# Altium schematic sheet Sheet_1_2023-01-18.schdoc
size 318 x 214 mm
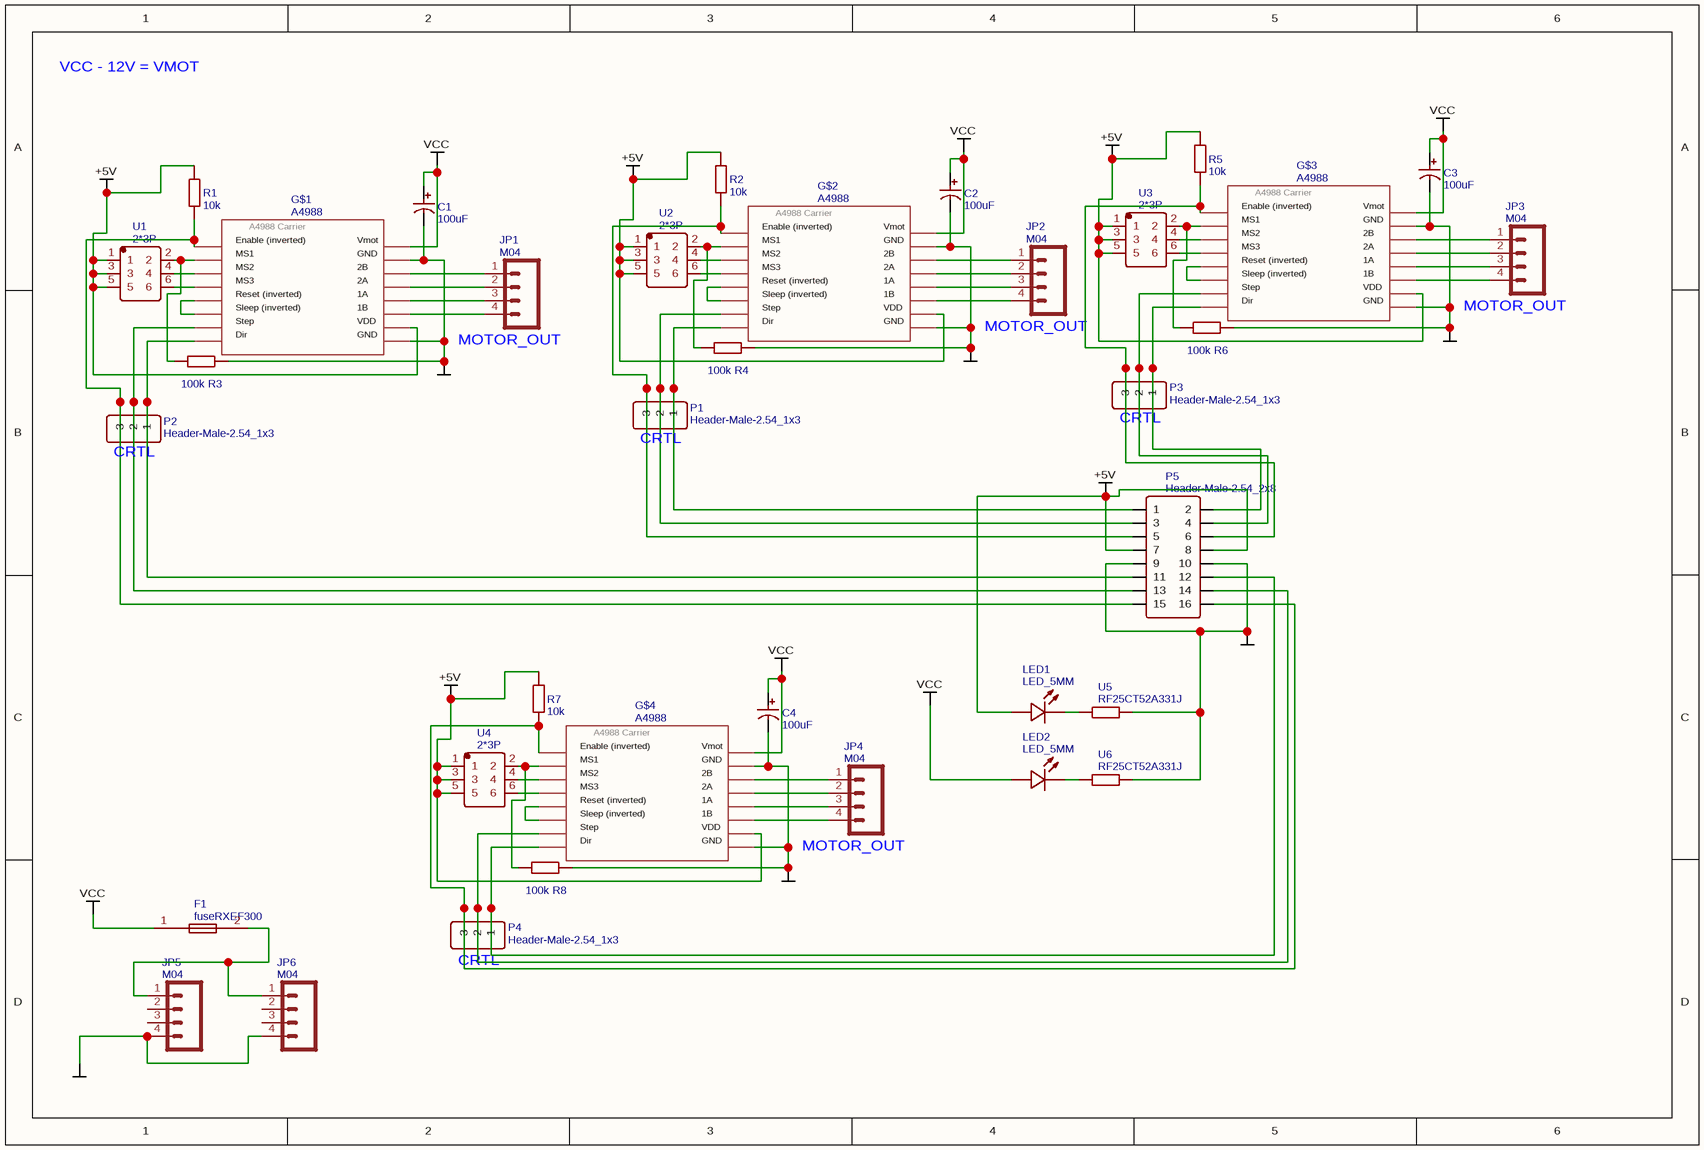
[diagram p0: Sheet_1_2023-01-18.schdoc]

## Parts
C1  100uF  [CAP-8*5]
C2  100uF  [CAP-8*5]
C3  100uF  [CAP-8*5]
C4  100uF  [CAP-8*5]
F1  fuseRXEF300  [F-3.00A-60V]
G$1  A4988  [A4988BREAKOUT]
G$2  A4988  [A4988BREAKOUT]
G$3  A4988  [A4988BREAKOUT]
G$4  A4988  [A4988BREAKOUT]
JP1  M04  [SCREWTERMINAL-3.5MM-4]
JP2  M04  [SCREWTERMINAL-3.5MM-4]
JP3  M04  [SCREWTERMINAL-3.5MM-4]
JP4  M04  [SCREWTERMINAL-3.5MM-4]
JP5  M04  [SCREWTERMINAL-3.5MM-4]
JP6  M04  [SCREWTERMINAL-3.5MM-4]
LED1  LED_5MM  [LED 5MM]
LED2  LED_5MM  [LED 5MM]
P1  Header-Male-2.54_1x3  [HDR-3X1/2.54]
P2  Header-Male-2.54_1x3  [HDR-3X1/2.54]
P3  Header-Male-2.54_1x3  [HDR-3X1/2.54]
P4  Header-Male-2.54_1x3  [HDR-3X1/2.54]
P5  Header-Male-2.54_2x8  [HDR-8X2/2.54]
R1  10k  [AXIAL-0.6]
R2  10k  [AXIAL-0.6]
R3  100k  [AXIAL-0.6]
R4  100k  [AXIAL-0.6]
R5  10k  [AXIAL-0.6]
R6  100k  [AXIAL-0.6]
R7  10k  [AXIAL-0.6]
R8  100k  [AXIAL-0.6]
U1  2*3P  [HDR-2.0-2X3P]
U2  2*3P  [HDR-2.0-2X3P]
U3  2*3P  [HDR-2.0-2X3P]
U4  2*3P  [HDR-2.0-2X3P]
U5  RF25CT52A331J  [AXIAL-6.5X2.3(1/4W)]
U6  RF25CT52A331J  [AXIAL-6.5X2.3(1/4W)]

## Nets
+5V: G$1.VDD G$2.VDD G$3.VDD G$4.VDD LED1.2(A) P5.7 P5.8 R1.2 R2.2 R5.2 R7.2 U1.1 U1.3 U1.5 U2.1 U2.3 U2.5 U3.1 U3.3 U3.5 U4.1 U4.3 U4.5
GND: C1.2 C2.2 C3.2 C4.2 G$1.GND G$1.GND@0(GND) G$2.GND G$2.GND@0(GND) G$3.GND G$3.GND@0(GND) G$4.GND G$4.GND@0(GND) JP5.4 JP6.4 P5.9 P5.10 R3.2 R4.2 R6.2 R8.2 U5.2 U6.2
VCC: C1.1 C2.1 C3.1 C4.1 F1.1 G$1.VMOT G$2.VMOT G$3.VMOT G$4.VMOT LED2.2(A)
NetF1_2: F1.2 JP5.1 JP6.1
NetG$1_1A: G$1.1A JP1.3
NetG$1_1B: G$1.1B JP1.4
NetG$1_2A: G$1.2A JP1.2
NetG$1_2B: G$1.2B JP1.1
NetG$1_DIR: G$1.DIR P2.1 P5.11
NetG$1_EN: G$1.EN P2.3 P5.15 R1.1
NetG$1_MS1: G$1.MS1 R3.1 U1.2
NetG$1_MS2: G$1.MS2 U1.4
NetG$1_MS3: G$1.MS3 U1.6
NetG$1_RST: G$1.RST G$1.SLP(SLEEP)
NetG$1_STEP: G$1.STEP P2.2 P5.13
NetG$2_1A: G$2.1A JP2.3
NetG$2_1B: G$2.1B JP2.4
NetG$2_2A: G$2.2A JP2.2
NetG$2_2B: G$2.2B JP2.1
NetG$2_DIR: G$2.DIR P1.1 P5.1
NetG$2_EN: G$2.EN P1.3 P5.5 R2.1
NetG$2_MS1: G$2.MS1 R4.1 U2.2
NetG$2_MS2: G$2.MS2 U2.4
NetG$2_MS3: G$2.MS3 U2.6
NetG$2_RST: G$2.RST G$2.SLP(SLEEP)
NetG$2_STEP: G$2.STEP P1.2 P5.3
NetG$3_1A: G$3.1A JP3.3
NetG$3_1B: G$3.1B JP3.4
NetG$3_2A: G$3.2A JP3.2
NetG$3_2B: G$3.2B JP3.1
NetG$3_DIR: G$3.DIR P3.1 P5.2
NetG$3_EN: G$3.EN P3.3 P5.6 R5.1
NetG$3_MS1: G$3.MS1 R6.1 U3.2
NetG$3_MS2: G$3.MS2 U3.4
NetG$3_MS3: G$3.MS3 U3.6
NetG$3_RST: G$3.RST G$3.SLP(SLEEP)
NetG$3_STEP: G$3.STEP P3.2 P5.4
NetG$4_1A: G$4.1A JP4.3
NetG$4_1B: G$4.1B JP4.4
NetG$4_2A: G$4.2A JP4.2
NetG$4_2B: G$4.2B JP4.1
NetG$4_DIR: G$4.DIR P4.1 P5.12
NetG$4_EN: G$4.EN P4.3 P5.16 R7.1
NetG$4_MS1: G$4.MS1 R8.1 U4.2
NetG$4_MS2: G$4.MS2 U4.4
NetG$4_MS3: G$4.MS3 U4.6
NetG$4_RST: G$4.RST G$4.SLP(SLEEP)
NetG$4_STEP: G$4.STEP P4.2 P5.14
NetLED1_1: LED1.1(K) U5.1
NetLED2_1: LED2.1(K) U6.1

Not connected (* = marked no-connect by the designer): JP5 2 3; JP6 2 3

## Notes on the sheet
- VCC - 12V = VMOT
- (near JP1) MOTOR_OUT
- (near JP2) MOTOR_OUT
- (near JP3) MOTOR_OUT
- (near P3) CRTL
- (near P2) CRTL
- (near P1) CRTL
- (near JP4) MOTOR_OUT
- (near P4) CRTL

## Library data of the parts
C1-C4 = 100uF: BOM_Manufacturer Part: 100uF 25V; BOM_Manufacturer: ReliaPro; nameAlias: Capacitance
F1 = fuseRXEF300: BOM_Manufacturer: TE Connectivity
G$1-G$4 = A4988: Contributor: KiwiDust
JP1-JP6 = M04: Contributor: SparkFun
LED1 LED2 = LED_5MM: Contributor: TomGeorge
P1-P4 = Header-Male-2.54_1x3: BOM_Manufacturer: BOOMELE; BOM_Manufacturer Part: Header2.54mm 1*3P
P5 = Header-Male-2.54_2x8: BOM_Manufacturer: BOOMELE; BOM_Manufacturer Part: Double row straight 2*8Headers  Pins 2.54mm
R1 R2 R5 R7 = 10k: BOM_Manufacturer: ResistorToday; BOM_Manufacturer Part: EWWR0001J100RT9; nameAlias: Value; Contributor: LCSC
R3 R4 R6 R8 = 100k: BOM_Manufacturer: ResistorToday; BOM_Manufacturer Part: EWWR0001J100RT9; nameAlias: Value; Contributor: LCSC
U1-U4 = 2*3P: BOM_Manufacturer: Boom Precision Elec; Contributor: LCSC
U5 U6 = RF25CT52A331J: BOM_Manufacturer: KOA Speer Elec; Contributor: LCSC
